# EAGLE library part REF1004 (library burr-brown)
Micropower Voltage Reference
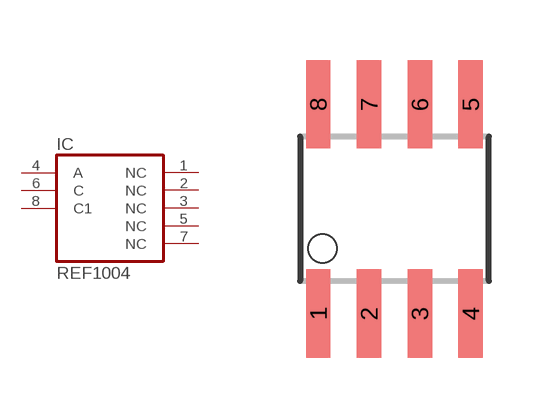
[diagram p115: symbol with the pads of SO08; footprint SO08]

Designator prefix IC

## REF1004U (MF: TEXAS INSTRUMENTS; MPN: REF1004C-1.2; OC_FARNELL: 1296022; OC_NEWARK: 75C7399)  [SO08]
1  NC  nc
2  NC  nc
3  NC  nc
4  A  pas
5  NC  nc
6  C  pas
7  NC  nc
8  C1  pas

## Footprint SO08 (pad centres in mm)
Small Outline Package
smd 0.61 x 2.21: 1 -1.905,-2.616; 2 -0.635,-2.616; 3 0.635,-2.616; 4 1.905,-2.616; 5 1.905,2.616; 6 0.635,2.616; 7 -0.635,2.616; 8 -1.905,2.616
